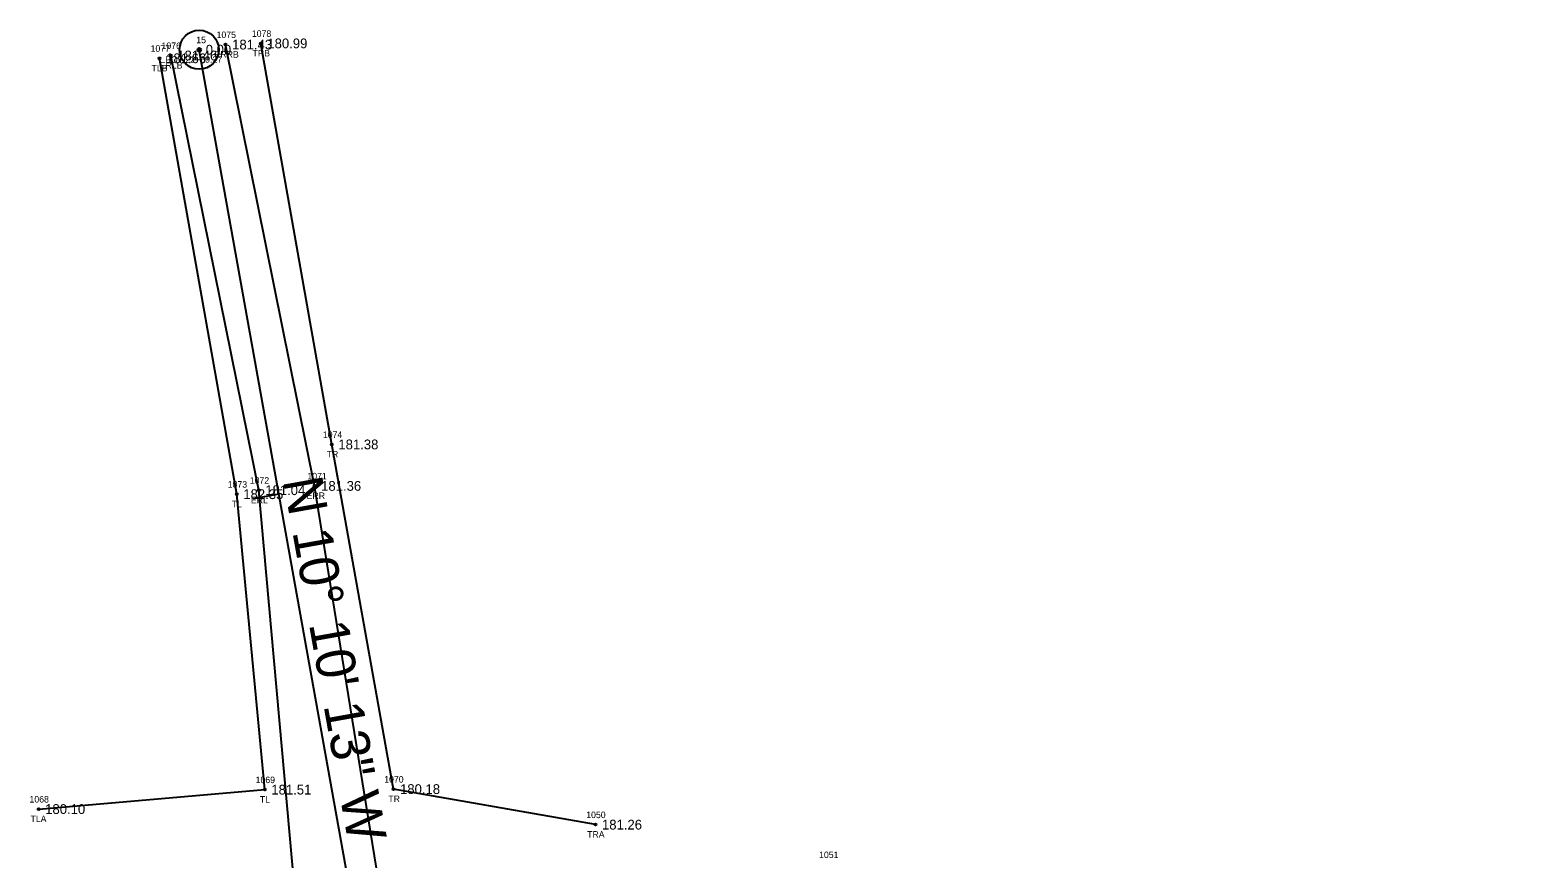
# Model space of a CAD drawing. Extents: x 1970735 to 1971583, y 794736 to 795766.
# Drawn here: x 1970761.4 to 1970992.6, y 795638.9 to 795766 of the extents above; entities that cross this region are included whole.
import ezdxf

# ---------------------------------------------------------------- set-up
doc = ezdxf.new("R2010")
doc.units = 0
for name, color, linetype in [('RD_EX_H2O_txCode', 7, 'Continuous'), ('RD_EX_Road', 7, 'Continuous'), ('RD_EX_Road_txCode', 7, 'Continuous'), ('RD_EX_TX_Road_ELEV', 7, 'Continuous'), ('RD_EX_TX_VEG_ELEV', 7, 'Continuous'), ('RD_EX_VEG', 7, 'Continuous'), ('RD_EX_VEG_txCode', 7, 'Continuous'), ('RD_HC_Cl', 7, 'Continuous'), ('RD_HC_Data', 7, 'Continuous'), ('RD_HC_Data_Tic', 7, 'Continuous'), ('RD_HC_Survey_ELEV', 7, 'Continuous'), ('RD_HC_txCode', 7, 'Continuous'), ('RD_SMD_Locator', 7, 'Continuous')]:
    doc.layers.add(name, color=color, linetype=linetype)

msp = doc.modelspace()

# ---------------------------------------------------------------- linework, layer by layer
at = {"layer": 'RD_EX_Road'}
for points in [[(1971550.5, 794861.13), (1971472.2, 794904.32), (1971401.49, 794943.08), (1971346.58, 794975.73), (1971286.05, 795024.56), (1971217.92, 795079.41), (1971172.76, 795121.06), (1971082.31, 795221.27), (1971017.96, 795288.13), (1970931.75, 795387.33), (1970878.11, 795452.95), (1970856.35, 795489.48), (1970840.29, 795529.45), (1970827.57, 795574.31), (1970814.81, 795635.62), (1970805.04, 795696.13), (1970791.39, 795763.83)], [(1970763.79, 795623.75), (1970802, 795634), (1970796.47, 795695.47), (1970782.97, 795762.15)]]:
    msp.add_lwpolyline(points, dxfattribs=at)
at = {"layer": 'RD_EX_VEG'}
for points in [[(1970848.11, 795644.17), (1970817.14, 795649.62), (1970807.68, 795702.49), (1970796.79, 795764.01)], [(1970762.72, 795646.56), (1970797.4, 795649.54), (1970793.1, 795694.86), (1970781.27, 795761.72)]]:
    msp.add_lwpolyline(points, dxfattribs=at)
at = {"layer": 'RD_HC_Cl'}
msp.add_line((1970820.17, 795580.04), (1970787.34, 795763.04), dxfattribs=at)
at = {"layer": 'RD_HC_Data'}
for radius in [3, 0.282]:
    msp.add_circle((1970787.34, 795763.04), radius, dxfattribs=at)
at = {"layer": 'RD_HC_Data_Tic'}
msp.add_line((1970799.57, 795694.86), (1970795.63, 795694.15), dxfattribs=at)
at = {"layer": 'RD_SMD_Locator'}
for centre in [(1970782.97, 795762.15), (1970787.34, 795763.04), (1970791.39, 795763.83), (1970796.79, 795764.01), (1970781.27, 795761.72), (1970807.68, 795702.49), (1970796.47, 795695.47), (1970805.04, 795696.13), (1970793.1, 795694.86), (1970797.4, 795649.54), (1970817.14, 795649.62), (1970762.72, 795646.56), (1970848.11, 795644.17)]:
    msp.add_circle(centre, 0.15, dxfattribs=at)

# ---------------------------------------------------------------- texts
at = {"layer": 'RD_EX_H2O_txCode'}
msp.add_text('1051', height=1, dxfattribs=at).set_placement((1970882.4, 795639.04))
at = {"layer": 'RD_EX_Road_txCode'}
for s, p in [('1075', (1970790, 795764.83)), ('1076', (1970781.56, 795763.15)), ('ERRB', (1970789.69, 795761.83)), ('ERLB', (1970781.29, 795760.15)), ('1072', (1970795.09, 795696.47)), ('1071', (1970803.93, 795697.13)), ('ERR', (1970803.81, 795694.13)), ('ERL', (1970795.27, 795693.47))]:
    msp.add_text(s, height=1, dxfattribs=at).set_placement(p)
at = {"layer": 'RD_EX_TX_Road_ELEV'}
for s, p in [('181.43', (1970792.39, 795763.08)), ('181.46', (1970783.97, 795761.4)), ('181.04', (1970797.47, 795694.72)), ('181.36', (1970806.04, 795695.38))]:
    msp.add_text(s, height=1.5, dxfattribs=at).set_placement(p)
at = {"layer": 'RD_EX_TX_VEG_ELEV'}
for s, p in [('180.99', (1970797.79, 795763.26)), ('181.66', (1970782.27, 795760.97)), ('181.38', (1970808.68, 795701.74)), ('182.35', (1970794.1, 795694.11)), ('181.51', (1970798.4, 795648.79)), ('180.18', (1970818.14, 795648.87)), ('180.10', (1970763.72, 795645.81)), ('181.26', (1970849.11, 795643.42))]:
    msp.add_text(s, height=1.5, dxfattribs=at).set_placement(p)
at = {"layer": 'RD_EX_VEG_txCode'}
for s, p in [('1078', (1970795.41, 795765.01)), ('1077', (1970779.88, 795762.72)), ('TRB', (1970795.52, 795762.01)), ('TLB', (1970780.02, 795759.72)), ('1074', (1970806.3, 795703.49)), ('TR', (1970806.89, 795700.49)), ('1073', (1970791.71, 795695.86)), ('TL', (1970792.33, 795692.86)), ('1069', (1970795.99, 795650.54)), ('1070', (1970815.71, 795650.62)), ('1068', (1970761.31, 795647.56)), ('TL', (1970796.63, 795647.54)), ('TR', (1970816.34, 795647.62)), ('TLA', (1970761.46, 795644.56)), ('1050', (1970846.69, 795645.17)), ('TRA', (1970846.83, 795642.17))]:
    msp.add_text(s, height=1, dxfattribs=at).set_placement(p)
at = {"layer": 'RD_HC_Data'}
msp.add_text('N 10%%d 10\' 13" W', height=6, rotation=280.1703, dxfattribs=at).set_placement((1970800.2, 795696.99))
at = {"layer": 'RD_HC_Survey_ELEV'}
msp.add_text('0.00', height=1.5, dxfattribs=at).set_placement((1970788.34, 795762.29))
at = {"layer": 'RD_HC_txCode'}
for s, p in [('15', (1970786.89, 795764.04)), ('POT 22+69.27', (1970782.12, 795761.04))]:
    msp.add_text(s, height=1, dxfattribs=at).set_placement(p)

doc.saveas('drawing.dxf')
